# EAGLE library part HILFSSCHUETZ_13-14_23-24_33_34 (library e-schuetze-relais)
Hilfsschütz mit 3 Schließern
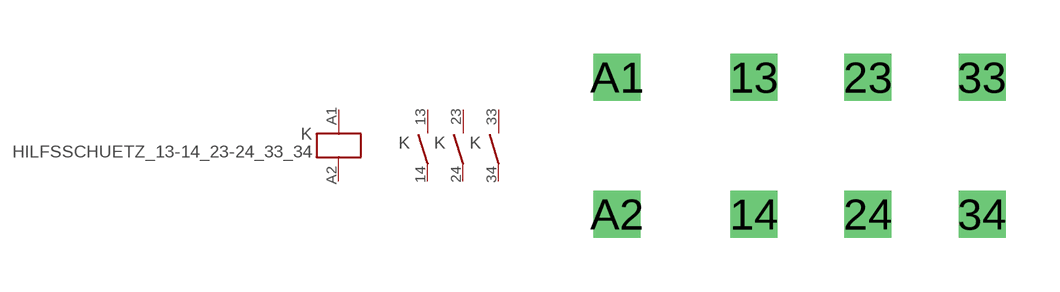
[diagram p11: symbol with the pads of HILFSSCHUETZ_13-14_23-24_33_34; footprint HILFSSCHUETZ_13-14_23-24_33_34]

Designator prefix K; gates G$1=SPULE 1=SCHLIESSER 2=SCHLIESSER 3=SCHLIESSER

## HILFSSCHUETZ_13-14_23-24_33_34  [HILFSSCHUETZ_13-14_23-24_33_34]
13  1:3  pas
14  1:4  pas
23  2:3  pas
24  2:4  pas
33  3:3  pas
34  3:4  pas
A1  G$1:A1  in
A2  G$1:A2  in

## Footprint HILFSSCHUETZ_13-14_23-24_33_34 (pad centres in mm)
Dummy
drill 0.8 square: 13 0,1.905; 14 0,-1.905; 23 3.175,1.905; 24 3.175,-1.905; 33 6.35,1.905; 34 6.35,-1.905; A1 -3.81,1.905; A2 -3.81,-1.905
